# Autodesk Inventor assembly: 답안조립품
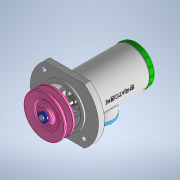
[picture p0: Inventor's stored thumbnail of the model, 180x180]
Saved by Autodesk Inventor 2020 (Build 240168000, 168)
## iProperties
Created: 2022-05
Part Number: 답안조립품
Document SubType Name: Assembly
Designer: Student
Author: Student
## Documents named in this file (20)
- C:\Users\Student\Desktop\720506V1025\답안조립품.iam
- C:\Users\Student\Desktop\720506V1025\본체.ipt
- C:\Users\Student\Desktop\720506V1025\개스킷.ipt
- C:\Users\Student\Desktop\720506V1025\사이드 커버.ipt
- 사이드 커버.ipt
- C:\Users\Student\Desktop\720506V1025\축.ipt
- C:\Users\Student\Desktop\720506V1025\멈춤링 15 x 1.ipt
- C:\Users\Student\Desktop\720506V1025\베어링 6202.ipt
- C:\Users\Student\Desktop\720506V1025\멈춤링 35 x 1.6.ipt
- C:\Users\Student\Desktop\720506V1025\부시1.ipt
- C:\Users\Student\Desktop\720506V1025\부시2.ipt
- C:\Users\Student\Desktop\720506V1025\와셔 10 x 21.ipt
- C:\Users\Student\Desktop\720506V1025\너트 M10.ipt
- C:\Users\Student\Desktop\720506V1025\V-벨트풀리.ipt
- C:\Users\Student\Desktop\720506V1025\키 4 x 4.ipt
- C:\Users\Student\Desktop\720506V1025\와셔 4 x 16.ipt
- C:\Users\Student\Desktop\720506V1025\멈춤나사 M3.ipt
- C:\Users\Student\Desktop\720506V1025\볼트 M4 x 10.ipt
- C:\Users\Student\Desktop\720506V1025\탑 커버.ipt
- C:\Users\Student\Desktop\720506V1025\십자볼트 M3 x 10.ipt
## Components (3 placed, 3 different names)
1. 개스킷:1
2. V-벨트풀리:1
3. ISO 4017 M4 x 10:1
